// Mitsubishi GX Works2 project: 65用子程序做单键启停   PLC: FX3U/FX3UC

PROGRAM MAIN
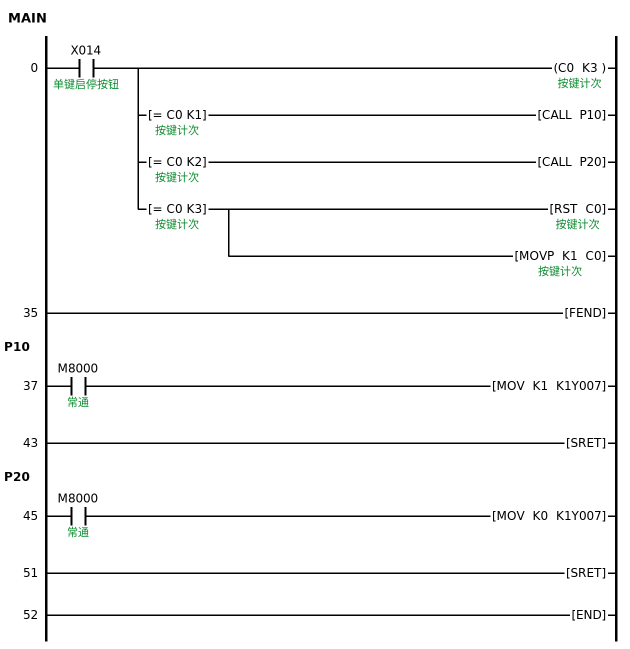
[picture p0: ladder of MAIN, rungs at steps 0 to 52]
0     LD      X014  ; 单键启停按钮
      OUT     C0 K3  ; 按键计次
      MPS
      AND=    C0 K1  ; 按键计次
      CALL    P10
      MRD
      AND=    C0 K2  ; 按键计次
      CALL    P20
      MPP
      AND=    C0 K3  ; 按键计次
      RST     C0  ; 按键计次
      MOVP    K1 C0
35    FEND
      P10
37    LD      M8000  ; 常通
      MOV     K1 K1Y007
43    SRET
      P20
45    LD      M8000  ; 常通
      MOV     K0 K1Y007
51    SRET
52    END
END_PROGRAM
